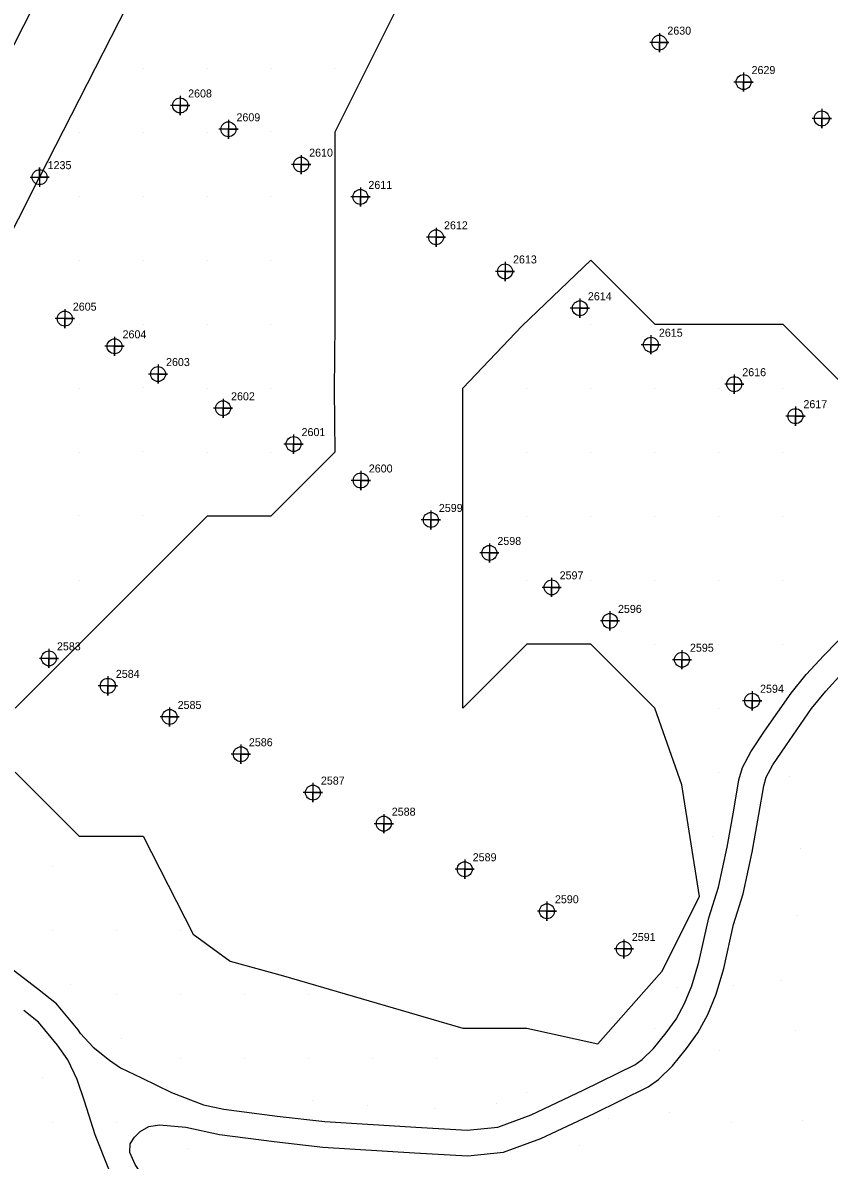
# Model space of a CAD drawing. Extents: x 2062781 to 2066835, y 358981 to 366501.
# Drawn here: x 2064641.3 to 2064893.4, y 362258.5 to 362613.9 of the extents above; entities that cross this region are included whole.
import ezdxf

# ---------------------------------------------------------------- set-up
doc = ezdxf.new("R2010")
doc.units = 0
for name, color, linetype in [('Exist DTM Regular Point CELL', 7, 'Continuous'), ('Exist DTM Regular Point Cogo Number', 7, 'Continuous'), ('Exist Structure Major Deck Tunnel Box Culvert', 7, 'Continuous'), ('Exist Structure Major Deck Tunnel Box Culvert Cogo Number', 7, 'Continuous'), ('Exist Structure Major Deck Tunnel Box Culvert Cogo Point CELL', 7, 'Continuous'), ('PH Exist DTM Breakline', 7, 'Continuous'), ('PH Exist DTM Point', 7, 'Continuous')]:
    doc.layers.add(name, color=color, linetype=linetype)

msp = doc.modelspace()

# ---------------------------------------------------------------- linework, layer by layer
at = {"layer": 'Exist DTM Regular Point CELL'}
for points in [[(2064840.27, 362610.7), (2064840.27, 362604.7), (2064840.27, 362607.7), (2064843.27, 362607.7), (2064837.27, 362607.7)], [(2064866.6, 362598.38), (2064866.6, 362592.38), (2064866.6, 362595.38), (2064869.6, 362595.38), (2064863.6, 362595.38)], [(2064690.46, 362591.07), (2064690.46, 362585.07), (2064690.46, 362588.07), (2064693.46, 362588.07), (2064687.46, 362588.07)], [(2064891.04, 362587.01), (2064891.04, 362581.01), (2064891.04, 362584.01), (2064894.04, 362584.01), (2064888.04, 362584.01)], [(2064705.57, 362583.61), (2064705.57, 362577.61), (2064705.57, 362580.61), (2064708.57, 362580.61), (2064702.57, 362580.61)], [(2064728.29, 362572.57), (2064728.29, 362566.57), (2064728.29, 362569.57), (2064731.29, 362569.57), (2064725.29, 362569.57)], [(2064746.82, 362562.48), (2064746.82, 362556.48), (2064746.82, 362559.48), (2064749.82, 362559.48), (2064743.82, 362559.48)], [(2064770.45, 362549.86), (2064770.45, 362543.86), (2064770.45, 362546.86), (2064773.45, 362546.86), (2064767.45, 362546.86)], [(2064792.02, 362539.2), (2064792.02, 362533.2), (2064792.02, 362536.2), (2064795.02, 362536.2), (2064789.02, 362536.2)], [(2064815.43, 362527.7), (2064815.43, 362521.7), (2064815.43, 362524.7), (2064818.43, 362524.7), (2064812.43, 362524.7)], [(2064654.41, 362524.45), (2064654.41, 362518.45), (2064654.41, 362521.45), (2064657.41, 362521.45), (2064651.41, 362521.45)], [(2064669.96, 362515.8), (2064669.96, 362509.8), (2064669.96, 362512.8), (2064672.96, 362512.8), (2064666.96, 362512.8)], [(2064837.63, 362516.3), (2064837.63, 362510.3), (2064837.63, 362513.3), (2064840.63, 362513.3), (2064834.63, 362513.3)], [(2064683.55, 362507.13), (2064683.55, 362501.13), (2064683.55, 362504.13), (2064686.55, 362504.13), (2064680.55, 362504.13)], [(2064863.7, 362503.96), (2064863.7, 362497.96), (2064863.7, 362500.96), (2064866.7, 362500.96), (2064860.7, 362500.96)], [(2064703.88, 362496.43), (2064703.88, 362490.43), (2064703.88, 362493.43), (2064706.88, 362493.43), (2064700.88, 362493.43)], [(2064882.81, 362493.97), (2064882.81, 362487.97), (2064882.81, 362490.97), (2064885.81, 362490.97), (2064879.81, 362490.97)], [(2064725.92, 362485.25), (2064725.92, 362479.25), (2064725.92, 362482.25), (2064728.92, 362482.25), (2064722.92, 362482.25)], [(2064746.94, 362473.87), (2064746.94, 362467.87), (2064746.94, 362470.87), (2064749.94, 362470.87), (2064743.94, 362470.87)], [(2064768.84, 362461.54), (2064768.84, 362455.54), (2064768.84, 362458.54), (2064771.84, 362458.54), (2064765.84, 362458.54)], [(2064787.14, 362451.23), (2064787.14, 362445.23), (2064787.14, 362448.23), (2064790.14, 362448.23), (2064784.14, 362448.23)], [(2064806.6, 362440.48), (2064806.6, 362434.48), (2064806.6, 362437.48), (2064809.6, 362437.48), (2064803.6, 362437.48)], [(2064824.83, 362429.99), (2064824.83, 362423.99), (2064824.83, 362426.99), (2064827.83, 362426.99), (2064821.83, 362426.99)], [(2064649.45, 362418.29), (2064649.45, 362412.29), (2064649.45, 362415.29), (2064652.45, 362415.29), (2064646.45, 362415.29)], [(2064847.34, 362417.86), (2064847.34, 362411.86), (2064847.34, 362414.86), (2064850.34, 362414.86), (2064844.34, 362414.86)], [(2064667.86, 362409.69), (2064667.86, 362403.69), (2064667.86, 362406.69), (2064670.86, 362406.69), (2064664.86, 362406.69)], [(2064869.26, 362405.04), (2064869.26, 362399.04), (2064869.26, 362402.04), (2064872.26, 362402.04), (2064866.26, 362402.04)], [(2064687.18, 362399.98), (2064687.18, 362393.98), (2064687.18, 362396.98), (2064690.18, 362396.98), (2064684.18, 362396.98)], [(2064709.45, 362388.32), (2064709.45, 362382.32), (2064709.45, 362385.32), (2064712.45, 362385.32), (2064706.45, 362385.32)], [(2064731.97, 362376.34), (2064731.97, 362370.34), (2064731.97, 362373.34), (2064734.97, 362373.34), (2064728.97, 362373.34)], [(2064754.12, 362366.63), (2064754.12, 362360.63), (2064754.12, 362363.63), (2064757.12, 362363.63), (2064751.12, 362363.63)], [(2064779.43, 362352.39), (2064779.43, 362346.39), (2064779.43, 362349.39), (2064782.43, 362349.39), (2064776.43, 362349.39)], [(2064805.13, 362339.26), (2064805.13, 362333.26), (2064805.13, 362336.26), (2064808.13, 362336.26), (2064802.13, 362336.26)], [(2064829.17, 362327.47), (2064829.17, 362321.47), (2064829.17, 362324.47), (2064832.17, 362324.47), (2064826.17, 362324.47)]]:
    msp.add_lwpolyline(points, dxfattribs=at)
for centre in [(2064840.27, 362607.7), (2064866.6, 362595.38), (2064690.46, 362588.07), (2064891.04, 362584.01), (2064705.57, 362580.61), (2064728.29, 362569.57), (2064746.82, 362559.48), (2064770.45, 362546.86), (2064792.02, 362536.2), (2064815.43, 362524.7), (2064654.41, 362521.45), (2064669.96, 362512.8), (2064837.63, 362513.3), (2064683.55, 362504.13), (2064863.7, 362500.96), (2064703.88, 362493.43), (2064882.81, 362490.97), (2064725.92, 362482.25), (2064746.94, 362470.87), (2064768.84, 362458.54), (2064787.14, 362448.23), (2064806.6, 362437.48), (2064824.83, 362426.99), (2064649.45, 362415.29), (2064847.34, 362414.86), (2064667.86, 362406.69), (2064869.26, 362402.04), (2064687.18, 362396.98), (2064709.45, 362385.32), (2064731.97, 362373.34), (2064754.12, 362363.63), (2064779.43, 362349.39), (2064805.13, 362336.26), (2064829.17, 362324.47)]:
    msp.add_circle(centre, 2.34, dxfattribs=at)
at = {"layer": 'Exist Structure Major Deck Tunnel Box Culvert'}
msp.add_line((2064619.37, 362512.07), (2064646.54, 362565.66), dxfattribs=at)
for points in [[(2064623.4, 362577.44), (2064650.62, 362630.92), (2064677.82, 362684.31), (2064698.23, 362724.56), (2064718.6, 362764.59), (2064738.99, 362804.71), (2064759.36, 362844.81), (2064779.84, 362884.94), (2064800.12, 362924.98), (2064820.56, 362965.07), (2064840.94, 363005.22), (2064861.36, 363045.25), (2064881.68, 363085.34), (2064902.1, 363125.46), (2064922.64, 363165.68)], [(2064945.77, 363153.79), (2064925.42, 363113.93), (2064904.9, 363073.71), (2064884.54, 363033.52), (2064864.2, 362993.6), (2064843.79, 362953.32), (2064823.4, 362913.38), (2064803.04, 362873.21), (2064782.63, 362833.19), (2064762.2, 362793.01), (2064741.73, 362752.83), (2064721.36, 362712.82), (2064700.92, 362672.65), (2064673.77, 362619.11), (2064646.54, 362565.66)]]:
    msp.add_lwpolyline(points, dxfattribs=at)
at = {"layer": 'Exist Structure Major Deck Tunnel Box Culvert Cogo Point CELL'}
msp.add_lwpolyline([(2064643.54, 362565.66), (2064649.54, 362565.66), (2064646.54, 362565.66), (2064646.54, 362568.66), (2064646.54, 362562.66)], dxfattribs=at)
msp.add_lwpolyline([(2064643.54, 362565.66), (2064649.54, 362565.66), (2064646.54, 362565.66), (2064646.54, 362568.66), (2064646.54, 362562.66)], dxfattribs=at)
msp.add_lwpolyline([(2064643.54, 362565.66), (2064649.54, 362565.66), (2064646.54, 362565.66), (2064646.54, 362568.66), (2064646.54, 362562.66)], dxfattribs=at)
msp.add_circle((2064646.54, 362565.66), 2.34, dxfattribs=at)
msp.add_circle((2064646.54, 362565.66), 2.34, dxfattribs=at)
msp.add_circle((2064646.54, 362565.66), 2.34, dxfattribs=at)
at = {"layer": 'PH Exist DTM Breakline'}
for points in [[(2064938.86, 362939.76), (2064898.86, 362919.76), (2064878.86, 362899.76), (2064858.86, 362859.76), (2064878.86, 362839.76), (2064878.86, 362819.76), (2064878.86, 362799.76), (2064858.86, 362759.76), (2064838.86, 362739.76), (2064818.86, 362719.76), (2064798.86, 362679.76), (2064798.86, 362659.76), (2064778.86, 362639.76), (2064758.86, 362619.76), (2064738.86, 362579.76), (2064738.86, 362559.76), (2064738.86, 362539.76), (2064738.86, 362519.76), (2064738.6, 362499.33), (2064738.86, 362479.76), (2064718.86, 362459.76), (2064698.86, 362459.76), (2064658.86, 362419.76)], [(2064638.86, 362379.76), (2064658.86, 362359.76), (2064678.86, 362359.76), (2064694.51, 362329.05), (2064706.05, 362320.68), (2064722.74, 362316.04), (2064778.86, 362299.76), (2064798.86, 362299.76), (2064821.07, 362294.8), (2064841, 362317.46), (2064852.87, 362340.87), (2064847.31, 362375.76), (2064838.86, 362399.76), (2064818.86, 362419.76), (2064798.86, 362419.76), (2064778.86, 362399.76), (2064778.86, 362419.76), (2064778.84, 362439.72), (2064778.86, 362459.76), (2064778.86, 362479.76), (2064778.86, 362499.76), (2064797.36, 362519.22), (2064818.86, 362539.76), (2064838.86, 362519.76), (2064858.86, 362519.76), (2064878.86, 362519.76), (2064898.86, 362499.76)], [(2064509.03, 362447.72), (2064511.16, 362434.78), (2064512.93, 362427.06), (2064517.72, 362416.03), (2064522.12, 362408.21), (2064527.8, 362400.56), (2064533.23, 362393.47), (2064557, 362369.81), (2064564.43, 362359.8), (2064567.27, 362352.54), (2064569.44, 362346.09), (2064569.91, 362345.55), (2064572.7, 362344.28), (2064588.12, 362339.48), (2064604, 362335.28), (2064613.4, 362331.32), (2064629.28, 362323.5), (2064638.28, 362317.97), (2064645.86, 362312.07)], [(2064816.45, 362280.31), (2064832.56, 362288.27), (2064834.95, 362289.92), (2064838.44, 362293.33), (2064842.4, 362298.22), (2064845.52, 362302.55), (2064848.16, 362307.4), (2064850.42, 362312.98), (2064852.66, 362320.4), (2064855.75, 362334.18), (2064858.76, 362343.8), (2064861.47, 362356.27), (2064863.52, 362367.85), (2064865.12, 362377.3), (2064866.26, 362381.16), (2064868.89, 362386.08), (2064873.15, 362392.49), (2064881.48, 362404.44), (2064886.21, 362410.28), (2064891.65, 362416.19), (2064899.96, 362424.64)], [(2064658.86, 362419.76), (2064638.86, 362399.76)], [(2064819.87, 362273.08), (2064836.76, 362281.44), (2064840.05, 362283.73), (2064844.36, 362287.93), (2064848.76, 362293.36), (2064852.31, 362298.29), (2064855.4, 362303.98), (2064857.98, 362310.31), (2064860.41, 362318.37), (2064863.48, 362332.11), (2064866.51, 362341.75), (2064869.32, 362354.73), (2064871.4, 362366.49), (2064872.93, 362375.49), (2064873.7, 362378.11), (2064875.76, 362381.97), (2064879.76, 362387.98), (2064887.88, 362399.63), (2064892.27, 362405.05), (2064897.45, 362410.67)], [(2064659.32, 362298.09), (2064658.55, 362299.21), (2064651.83, 362307.3), (2064645.91, 362312.04)], [(2064717.64, 362201.61), (2064717.23, 362202.13), (2064707.2, 362212.45), (2064695.51, 362223.09), (2064688.98, 362230.25), (2064680.53, 362238.59), (2064673.8, 362246.6), (2064668.21, 362255.68), (2064663.93, 362266.42), (2064660.59, 362276.93), (2064658.23, 362283.66), (2064655.31, 362289.82), (2064652.17, 362294.37), (2064646.19, 362301.56), (2064641.57, 362305.26)], [(2064659.32, 362298.09), (2064663.32, 362293.76), (2064668.4, 362289.74), (2064671.8, 362287.36), (2064678.4, 362284.18), (2064687.75, 362279.66), (2064697.79, 362275.79)], [(2064697.79, 362275.79), (2064704.12, 362274.43), (2064720.82, 362272.2), (2064735.74, 362270.54), (2064764.18, 362268.79), (2064780.22, 362267.85), (2064789.75, 362268.79), (2064800.17, 362272.62), (2064816.45, 362280.31)], [(2064692.2, 362268.81), (2064702.75, 362266.54), (2064719.85, 362264.26), (2064735.05, 362262.57), (2064763.7, 362260.8), (2064780.39, 362259.82), (2064791.55, 362260.93), (2064803.27, 362265.23), (2064819.87, 362273.08)], [(2064679.47, 362252.65), (2064676.45, 362257.16), (2064674.7, 362260.91), (2064674.8, 362263.56), (2064676.22, 362265.64), (2064677.96, 362267.43), (2064680.66, 362269.03), (2064683.97, 362269.48), (2064692.2, 362268.81)]]:
    msp.add_lwpolyline(points, dxfattribs=at)
at = {"layer": 'PH Exist DTM Point'}
for p, q in [((2064678.86, 362599.76), (2064678.86, 362599.76)), ((2064698.86, 362599.76), (2064698.86, 362599.76)), ((2064718.89, 362599.74), (2064718.89, 362599.74)), ((2064738.86, 362599.76), (2064738.86, 362599.76)), ((2064658.86, 362579.76), (2064658.86, 362579.76)), ((2064678.86, 362579.76), (2064678.86, 362579.76)), ((2064698.86, 362579.76), (2064698.86, 362579.76)), ((2064718.82, 362579.78), (2064718.82, 362579.78)), ((2064658.86, 362559.76), (2064658.86, 362559.76)), ((2064678.86, 362559.76), (2064678.86, 362559.76)), ((2064698.86, 362559.76), (2064698.86, 362559.76)), ((2064718.86, 362559.76), (2064718.86, 362559.76)), ((2064658.86, 362539.76), (2064658.86, 362539.76)), ((2064678.86, 362539.76), (2064678.86, 362539.76)), ((2064698.86, 362539.76), (2064698.86, 362539.76)), ((2064718.86, 362539.76), (2064718.86, 362539.76)), ((2064658.86, 362519.76), (2064658.86, 362519.76)), ((2064678.86, 362519.76), (2064678.86, 362519.76)), ((2064698.86, 362519.76), (2064698.86, 362519.76)), ((2064718.86, 362519.76), (2064718.86, 362519.76)), ((2064818.86, 362519.76), (2064818.86, 362519.76)), ((2064658.86, 362499.76), (2064658.86, 362499.76)), ((2064678.87, 362499.79), (2064678.87, 362499.79)), ((2064698.86, 362499.76), (2064698.86, 362499.76)), ((2064718.86, 362499.76), (2064718.86, 362499.76)), ((2064798.86, 362499.76), (2064798.86, 362499.76)), ((2064818.86, 362499.76), (2064818.86, 362499.76)), ((2064838.86, 362499.76), (2064838.86, 362499.76)), ((2064858.86, 362499.76), (2064858.86, 362499.76)), ((2064878.86, 362499.76), (2064878.86, 362499.76)), ((2064658.86, 362479.76), (2064658.86, 362479.76)), ((2064678.79, 362479.79), (2064678.79, 362479.79)), ((2064698.86, 362479.76), (2064698.86, 362479.76)), ((2064718.86, 362479.76), (2064718.86, 362479.76)), ((2064798.86, 362479.76), (2064798.86, 362479.76)), ((2064818.86, 362479.76), (2064818.86, 362479.76)), ((2064838.86, 362479.76), (2064838.86, 362479.76)), ((2064858.86, 362479.76), (2064858.86, 362479.76)), ((2064878.86, 362479.76), (2064878.86, 362479.76)), ((2064658.63, 362459.83), (2064658.63, 362459.83)), ((2064678.65, 362459.86), (2064678.65, 362459.86)), ((2064798.86, 362459.76), (2064798.86, 362459.76)), ((2064818.86, 362459.76), (2064818.86, 362459.76)), ((2064838.86, 362459.76), (2064838.86, 362459.76)), ((2064858.86, 362459.76), (2064858.86, 362459.76)), ((2064878.86, 362459.76), (2064878.86, 362459.76)), ((2064658.86, 362439.76), (2064658.86, 362439.76)), ((2064798.86, 362439.76), (2064798.86, 362439.76)), ((2064818.86, 362439.76), (2064818.86, 362439.76)), ((2064838.86, 362439.76), (2064838.86, 362439.76)), ((2064858.86, 362439.76), (2064858.86, 362439.76)), ((2064878.86, 362439.76), (2064878.86, 362439.76)), ((2064838.86, 362419.76), (2064838.86, 362419.76)), ((2064858.86, 362419.76), (2064858.86, 362419.76)), ((2064878.86, 362419.76), (2064878.86, 362419.76)), ((2064876.61, 362407.28), (2064876.61, 362407.28)), ((2064858.86, 362399.76), (2064858.86, 362399.76)), ((2064858.86, 362379.76), (2064858.86, 362379.76)), ((2064880.94, 362378.44), (2064880.94, 362378.44)), ((2064856.76, 362359.62), (2064856.76, 362359.62)), ((2064884.33, 362356.02), (2064884.33, 362356.02)), ((2064650.65, 362350.27), (2064650.65, 362350.27)), ((2064883.33, 362334.83), (2064883.33, 362334.83)), ((2064650.65, 362330.27), (2064650.65, 362330.27)), ((2064670.65, 362330.27), (2064670.65, 362330.27)), ((2064690.65, 362330.27), (2064690.65, 362330.27)), ((2064656.17, 362313.4), (2064656.17, 362313.4)), ((2064845.81, 362312.44), (2064845.81, 362312.44)), ((2064863.57, 362312.99), (2064863.57, 362312.99)), ((2064878.53, 362314.48), (2064878.53, 362314.48)), ((2064670.65, 362310.27), (2064670.65, 362310.27)), ((2064690.65, 362310.27), (2064690.65, 362310.27)), ((2064710.68, 362310.26), (2064710.68, 362310.26)), ((2064730.61, 362310.29), (2064730.61, 362310.29)), ((2064838.86, 362299.76), (2064838.86, 362299.76)), ((2064882.89, 362299.08), (2064882.89, 362299.08)), ((2064672.15, 362296.36), (2064672.15, 362296.36)), ((2064859.04, 362292.89), (2064859.04, 362292.89)), ((2064690.65, 362290.27), (2064690.65, 362290.27)), ((2064710.65, 362290.27), (2064710.65, 362290.27)), ((2064730.65, 362290.27), (2064730.65, 362290.27)), ((2064750.65, 362290.27), (2064750.65, 362290.27)), ((2064770.65, 362290.27), (2064770.65, 362290.27)), ((2064647.32, 362284.43), (2064647.32, 362284.43)), ((2064731.71, 362276.97), (2064731.71, 362276.97)), ((2064798.86, 362279.76), (2064798.86, 362279.76)), ((2064749.05, 362275.7), (2064749.05, 362275.7)), ((2064770, 362274.75), (2064770, 362274.75)), ((2064789.29, 362276.09), (2064789.29, 362276.09)), ((2064843.59, 362273.41), (2064843.59, 362273.41)), ((2064650.65, 362270.27), (2064650.65, 362270.27)), ((2064670.65, 362270.27), (2064670.65, 362270.27)), ((2064824.45, 362271.35), (2064824.45, 362271.35)), ((2064862.91, 362270.21), (2064862.91, 362270.21)), ((2064885, 362270.82), (2064885, 362270.82)), ((2064815.19, 362263.17), (2064815.19, 362263.17)), ((2064692.76, 362262.18), (2064692.76, 362262.18))]:
    msp.add_line(p, q, dxfattribs=at)

# ---------------------------------------------------------------- texts
at = {"layer": 'Exist DTM Regular Point Cogo Number'}
for s, p in [('2630', (2064842.77, 362610.2)), ('2630', (2064842.77, 362610.2)), ('2630', (2064842.77, 362610.2)), ('2629', (2064869.1, 362597.88)), ('2629', (2064869.1, 362597.88)), ('2629', (2064869.1, 362597.88)), ('2608', (2064692.96, 362590.57)), ('2608', (2064692.96, 362590.57)), ('2608', (2064692.96, 362590.57)), ('2609', (2064708.07, 362583.11)), ('2609', (2064708.07, 362583.11)), ('2609', (2064708.07, 362583.11)), ('2610', (2064730.79, 362572.07)), ('2610', (2064730.79, 362572.07)), ('2610', (2064730.79, 362572.07)), ('2611', (2064749.32, 362561.98)), ('2611', (2064749.32, 362561.98)), ('2611', (2064749.32, 362561.98)), ('2612', (2064772.95, 362549.36)), ('2612', (2064772.95, 362549.36)), ('2612', (2064772.95, 362549.36)), ('2613', (2064794.52, 362538.7)), ('2613', (2064794.52, 362538.7)), ('2613', (2064794.52, 362538.7)), ('2614', (2064817.93, 362527.2)), ('2614', (2064817.93, 362527.2)), ('2614', (2064817.93, 362527.2)), ('2605', (2064656.91, 362523.95)), ('2605', (2064656.91, 362523.95)), ('2605', (2064656.91, 362523.95)), ('2615', (2064840.13, 362515.8)), ('2615', (2064840.13, 362515.8)), ('2615', (2064840.13, 362515.8)), ('2604', (2064672.46, 362515.3)), ('2604', (2064672.46, 362515.3)), ('2604', (2064672.46, 362515.3)), ('2603', (2064686.05, 362506.63)), ('2603', (2064686.05, 362506.63)), ('2603', (2064686.05, 362506.63)), ('2616', (2064866.2, 362503.46)), ('2616', (2064866.2, 362503.46)), ('2616', (2064866.2, 362503.46)), ('2602', (2064706.38, 362495.93)), ('2602', (2064706.38, 362495.93)), ('2602', (2064706.38, 362495.93)), ('2617', (2064885.31, 362493.47)), ('2617', (2064885.31, 362493.47)), ('2617', (2064885.31, 362493.47)), ('2601', (2064728.42, 362484.75)), ('2601', (2064728.42, 362484.75)), ('2601', (2064728.42, 362484.75)), ('2600', (2064749.44, 362473.37)), ('2600', (2064749.44, 362473.37)), ('2600', (2064749.44, 362473.37)), ('2599', (2064771.34, 362461.04)), ('2599', (2064771.34, 362461.04)), ('2599', (2064771.34, 362461.04)), ('2598', (2064789.64, 362450.73)), ('2598', (2064789.64, 362450.73)), ('2598', (2064789.64, 362450.73)), ('2597', (2064809.1, 362439.98)), ('2597', (2064809.1, 362439.98)), ('2597', (2064809.1, 362439.98)), ('2596', (2064827.33, 362429.49)), ('2596', (2064827.33, 362429.49)), ('2596', (2064827.33, 362429.49)), ('2583', (2064651.95, 362417.79)), ('2583', (2064651.95, 362417.79)), ('2583', (2064651.95, 362417.79)), ('2595', (2064849.84, 362417.36)), ('2595', (2064849.84, 362417.36)), ('2595', (2064849.84, 362417.36)), ('2584', (2064670.36, 362409.19)), ('2584', (2064670.36, 362409.19)), ('2584', (2064670.36, 362409.19)), ('2594', (2064871.76, 362404.54)), ('2594', (2064871.76, 362404.54)), ('2594', (2064871.76, 362404.54)), ('2585', (2064689.68, 362399.48)), ('2585', (2064689.68, 362399.48)), ('2585', (2064689.68, 362399.48)), ('2586', (2064711.95, 362387.82)), ('2586', (2064711.95, 362387.82)), ('2586', (2064711.95, 362387.82)), ('2587', (2064734.47, 362375.84)), ('2587', (2064734.47, 362375.84)), ('2587', (2064734.47, 362375.84)), ('2588', (2064756.62, 362366.13)), ('2588', (2064756.62, 362366.13)), ('2588', (2064756.62, 362366.13)), ('2589', (2064781.93, 362351.89)), ('2589', (2064781.93, 362351.89)), ('2589', (2064781.93, 362351.89)), ('2590', (2064807.63, 362338.76)), ('2590', (2064807.63, 362338.76)), ('2590', (2064807.63, 362338.76)), ('2591', (2064831.67, 362326.97)), ('2591', (2064831.67, 362326.97)), ('2591', (2064831.67, 362326.97))]:
    msp.add_text(s, height=2.5, dxfattribs=at).set_placement(p)
at = {"layer": 'Exist Structure Major Deck Tunnel Box Culvert Cogo Number'}
msp.add_text('1235', height=2.5, dxfattribs=at).set_placement((2064649.04, 362568.16))
msp.add_text('1235', height=2.5, dxfattribs=at).set_placement((2064649.04, 362568.16))
msp.add_text('1235', height=2.5, dxfattribs=at).set_placement((2064649.04, 362568.16))

doc.saveas('drawing.dxf')
